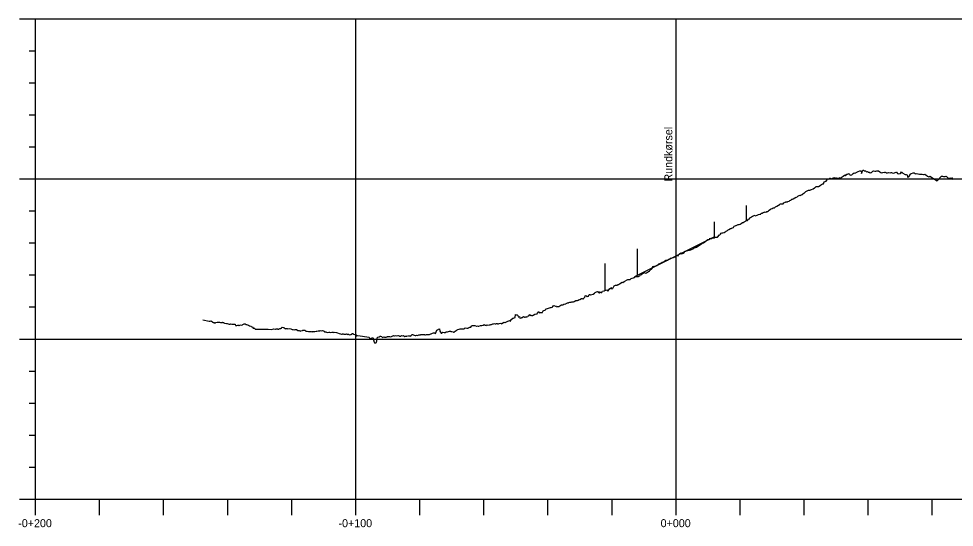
# Model space of a CAD drawing. Extents: x 0 to 513042, y 0 to 6212511.
# Drawn here: x 511927.8 to 512219.9, y 6211831.2 to 6211990 of the extents above; entities that cross this region are included whole.
import ezdxf

# ---------------------------------------------------------------- set-up
doc = ezdxf.new("R2010")
doc.units = 0
for name, color, linetype in [('TV_G_CL---', 7, 'Continuous'), ('TV_G_DTM_Exter', 7, 'Continuous'), ('TV_G_INF_SkrSg', 7, 'Continuous'), ('TV_L_---_Punkt', 7, 'Continuous'), ('TV_L_VER_Punkt', 7, 'Continuous')]:
    doc.layers.add(name, color=color, linetype=linetype)

msp = doc.modelspace()

# ---------------------------------------------------------------- linework, layer by layer
at = {"layer": 'TV_G_CL---'}
for q in [(511933.07, 6211990.01), (513033.07, 6211840.01)]:
    msp.add_line((511933.07, 6211840.01), q, dxfattribs=at)
at = {"layer": 'TV_G_DTM_Exter'}
for p, q in [((511928.07, 6211990.01), (511933.07, 6211990.01)), ((511928.07, 6211990.01), (511933.07, 6211990.01)), ((511931.07, 6211980.01), (511933.07, 6211980.01)), ((511931.07, 6211970.01), (511933.07, 6211970.01)), ((511931.07, 6211960.01), (511933.07, 6211960.01)), ((511931.07, 6211950.01), (511933.07, 6211950.01)), ((511928.07, 6211940.01), (511933.07, 6211940.01)), ((511931.07, 6211930.01), (511933.07, 6211930.01)), ((511931.07, 6211920.01), (511933.07, 6211920.01)), ((511931.07, 6211910.01), (511933.07, 6211910.01)), ((511931.07, 6211900.01), (511933.07, 6211900.01)), ((511928.07, 6211890.01), (511933.07, 6211890.01)), ((511931.07, 6211880.01), (511933.07, 6211880.01)), ((511931.07, 6211870.01), (511933.07, 6211870.01)), ((511931.07, 6211860.01), (511933.07, 6211860.01)), ((511931.07, 6211850.01), (511933.07, 6211850.01)), ((511928.07, 6211840.01), (511933.07, 6211840.01)), ((511933.07, 6211835.01), (511933.07, 6211840.01)), ((511953.07, 6211835.01), (511953.07, 6211840.01)), ((511973.07, 6211835.01), (511973.07, 6211840.01)), ((511993.07, 6211835.01), (511993.07, 6211840.01)), ((512013.07, 6211835.01), (512013.07, 6211840.01)), ((512033.07, 6211835.01), (512033.07, 6211840.01)), ((512053.07, 6211835.01), (512053.07, 6211840.01)), ((512073.07, 6211835.01), (512073.07, 6211840.01)), ((512093.07, 6211835.01), (512093.07, 6211840.01)), ((512113.07, 6211835.01), (512113.07, 6211840.01)), ((512133.07, 6211835.01), (512133.07, 6211840.01)), ((512153.07, 6211835.01), (512153.07, 6211840.01)), ((512173.07, 6211835.01), (512173.07, 6211840.01)), ((512193.07, 6211835.01), (512193.07, 6211840.01)), ((512213.07, 6211835.01), (512213.07, 6211840.01))]:
    msp.add_line(p, q, dxfattribs=at)
at = {"layer": 'TV_G_INF_SkrSg'}
msp.add_lwpolyline([(511985.36, 6211896.02), (511987.32, 6211895.56), (511987.55, 6211895.57), (511987.91, 6211895.64), (511988.47, 6211895.26), (511988.53, 6211895.2), (511988.73, 6211895.2), (511988.85, 6211895.15), (511989.11, 6211894.99), (511989.42, 6211895.15), (511989.78, 6211895.23), (511990.01, 6211895.23), (511990.53, 6211895.28), (511990.86, 6211895.16), (511991.04, 6211895.15), (511991.3, 6211895.18), (511991.48, 6211895.25), (511991.56, 6211895.12), (511991.78, 6211895.13), (511991.86, 6211895.08), (511992.12, 6211895.01), (511992.68, 6211894.84), (511992.88, 6211894.85), (511993.57, 6211894.62), (511993.87, 6211894.67), (511993.98, 6211894.71), (511994.41, 6211894.64), (511994.87, 6211894.67), (511995.19, 6211894.63), (511995.36, 6211894.6), (511995.53, 6211894.2), (511995.73, 6211894.2), (511995.9, 6211894.19), (511996.24, 6211894.34), (511996.42, 6211894.32), (511996.6, 6211894.24), (511996.69, 6211894.28), (511997.05, 6211894.44), (511997.35, 6211894.38), (511997.68, 6211894.43), (511997.82, 6211894.56), (511997.98, 6211894.64), (511998.26, 6211894.76), (511998.31, 6211894.7), (511998.53, 6211894.7), (511998.76, 6211894.53), (511998.89, 6211894.49), (511998.96, 6211894.53), (511999.58, 6211894.35), (511999.89, 6211894.14), (512000.3, 6211894.05), (512000.41, 6211893.89), (512000.86, 6211893.74), (512001.05, 6211893.42), (512001.47, 6211893.42), (512001.58, 6211893.27), (512001.67, 6211893.13), (512005.7, 6211893.04), (512006.73, 6211893.01), (512007.46, 6211893.15), (512007.86, 6211893.06), (512008.05, 6211893.06), (512008.22, 6211893.22), (512008.66, 6211893.15), (512008.77, 6211893.11), (512008.88, 6211893.08), (512009.09, 6211893.08), (512009.18, 6211893.22), (512009.31, 6211893.27), (512009.65, 6211893.33), (512009.89, 6211893.44), (512010.02, 6211893.75), (512010.04, 6211893.75), (512010.61, 6211893.58), (512011.13, 6211893.22), (512011.19, 6211893.25), (512011.54, 6211893.31), (512011.62, 6211893.26), (512011.81, 6211893.17), (512012.28, 6211893.3), (512012.77, 6211893.18), (512013.19, 6211893.03), (512013.49, 6211892.99), (512013.92, 6211892.92), (512014.18, 6211892.95), (512014.53, 6211892.94), (512014.94, 6211892.69), (512015.39, 6211892.62), (512015.8, 6211892.46), (512015.95, 6211892.53), (512016.42, 6211892.65), (512016.58, 6211892.81), (512017.09, 6211892.8), (512017.12, 6211892.8), (512017.5, 6211892.45), (512017.56, 6211892.48), (512017.85, 6211892.42), (512018.26, 6211892.36), (512018.62, 6211892.34), (512018.77, 6211892.33), (512018.9, 6211892.31), (512019.09, 6211892.31), (512019.46, 6211892.29), (512019.56, 6211892.34), (512019.74, 6211892.33), (512020.07, 6211892.32), (512020.27, 6211892.4), (512020.74, 6211892.43), (512020.87, 6211892.41), (512021.31, 6211892.52), (512021.88, 6211892.6), (512021.95, 6211892.63), (512022.28, 6211892.59), (512022.68, 6211892.69), (512022.76, 6211892.63), (512022.88, 6211892.59), (512023.16, 6211892.48), (512023.26, 6211892.3), (512023.76, 6211892.24), (512024.09, 6211892.01), (512024.62, 6211892.15), (512024.71, 6211892.12), (512024.83, 6211892.1), (512025.2, 6211892.08), (512025.6, 6211892.11), (512026, 6211892.19), (512026.01, 6211892.19), (512026.11, 6211892.09), (512026.5, 6211892.1), (512027.09, 6211892.07), (512027.41, 6211891.92), (512027.9, 6211891.73), (512028.27, 6211891.6), (512028.63, 6211891.56), (512028.79, 6211891.54), (512028.92, 6211891.59), (512029.12, 6211891.6), (512029.33, 6211891.54), (512029.41, 6211891.57), (512029.77, 6211891.54), (512030.04, 6211891.55), (512030.16, 6211891.61), (512030.58, 6211891.42), (512030.65, 6211891.55), (512030.86, 6211891.54), (512031.03, 6211891.31), (512031.48, 6211891.43), (512031.56, 6211891.47), (512032.02, 6211891.76), (512032.28, 6211891.72), (512032.35, 6211891.55), (512032.82, 6211891.45), (512032.94, 6211891.36), (512033.08, 6211891.35), (512033.26, 6211891.05), (512033.37, 6211891.02), (512033.72, 6211891.09), (512037.26, 6211890.56), (512037.39, 6211890.24), (512037.5, 6211890.21), (512037.92, 6211890.24), (512037.98, 6211890.27), (512038.21, 6211890.41), (512038.34, 6211890.49), (512038.79, 6211889.01), (512038.96, 6211888.86), (512039.34, 6211888.8), (512039.51, 6211888.94), (512039.81, 6211890.6), (512040.22, 6211890.68), (512040.5, 6211890.72), (512040.67, 6211890.9), (512040.81, 6211890.95), (512041.12, 6211890.78), (512041.43, 6211890.53), (512041.88, 6211890.72), (512042, 6211890.55), (512042.16, 6211890.62), (512042.57, 6211890.58), (512042.74, 6211890.64), (512042.87, 6211890.69), (512043.02, 6211890.76), (512043.2, 6211890.83), (512043.51, 6211890.76), (512043.59, 6211890.79), (512043.9, 6211890.74), (512044.23, 6211890.8), (512044.45, 6211890.9), (512044.87, 6211891.07), (512044.96, 6211891.02), (512045.1, 6211891.01), (512045.15, 6211891.03), (512045.42, 6211891.14), (512045.64, 6211891.04), (512046.18, 6211891.09), (512046.31, 6211891.07), (512046.62, 6211891.04), (512046.73, 6211890.93), (512046.84, 6211890.9), (512047.16, 6211890.93), (512047.35, 6211891.08), (512047.7, 6211891.04), (512047.96, 6211891.06), (512048.04, 6211891.01), (512048.33, 6211890.83), (512048.64, 6211890.87), (512049.04, 6211890.95), (512049.15, 6211891), (512049.21, 6211890.95), (512049.27, 6211890.97), (512049.44, 6211890.94), (512049.56, 6211891), (512049.92, 6211890.96), (512050.02, 6211890.93), (512050.32, 6211891.06), (512050.72, 6211891.37), (512050.85, 6211891.42), (512051, 6211891.33), (512051.29, 6211891.17), (512051.56, 6211891.11), (512051.85, 6211891.07), (512052.06, 6211891.16), (512052.46, 6211891.14), (512052.59, 6211891.22), (512052.8, 6211891.36), (512053.25, 6211891.28), (512053.31, 6211891.4), (512053.63, 6211891.38), (512053.83, 6211891.45), (512054.17, 6211891.41), (512054.53, 6211891.38), (512054.67, 6211891.28), (512054.82, 6211891.27), (512055.1, 6211891.38), (512055.7, 6211891.45), (512056.05, 6211891.43), (512056.52, 6211891.62), (512056.61, 6211891.66), (512057.07, 6211891.85), (512057.38, 6211891.98), (512057.66, 6211891.93), (512057.93, 6211891.78), (512058.39, 6211892.77), (512058.79, 6211893.02), (512058.89, 6211893.13), (512059.17, 6211893.16), (512059.34, 6211892.43), (512059.69, 6211891.88), (512059.91, 6211891.8), (512060.29, 6211892.12), (512060.64, 6211892.09), (512060.82, 6211892.08), (512061.01, 6211892.08), (512061.33, 6211892.3), (512061.56, 6211892.3), (512061.75, 6211892.3), (512062.02, 6211892.33), (512062.32, 6211892.46), (512062.64, 6211892.42), (512062.75, 6211892.38), (512063.08, 6211892.35), (512063.46, 6211892.26), (512063.59, 6211892.14), (512063.65, 6211892.17), (512063.8, 6211892.15), (512064.15, 6211892.47), (512064.42, 6211892.66), (512064.51, 6211892.7), (512064.57, 6211892.82), (512064.72, 6211892.88), (512064.96, 6211892.98), (512065.3, 6211893.04), (512065.65, 6211893.19), (512066.39, 6211893.24), (512066.76, 6211893.15), (512066.93, 6211893.22), (512067.17, 6211893.49), (512067.23, 6211893.49), (512067.77, 6211893.42), (512067.98, 6211893.42), (512068.16, 6211893.42), (512068.27, 6211893.47), (512068.64, 6211893.71), (512068.89, 6211893.73), (512068.97, 6211893.76), (512069.23, 6211894.04), (512069.34, 6211894.18), (512069.94, 6211894.19), (512070.09, 6211894.25), (512070.19, 6211894.2), (512070.71, 6211893.99), (512070.82, 6211894.04), (512071.12, 6211894.08), (512071.25, 6211894.05), (512071.48, 6211893.97), (512071.97, 6211894.18), (512072.46, 6211894.21), (512072.87, 6211894.38), (512073.19, 6211894.52), (512073.37, 6211894.33), (512073.53, 6211894.32), (512073.64, 6211894.28), (512074, 6211894.44), (512074.33, 6211894.33), (512074.68, 6211894.48), (512075.03, 6211894.45), (512075.2, 6211894.52), (512075.46, 6211894.55), (512075.87, 6211894.72), (512076.09, 6211894.73), (512076.41, 6211894.86), (512076.6, 6211894.77), (512076.76, 6211894.76), (512077.04, 6211894.88), (512077.18, 6211894.84), (512077.36, 6211894.76), (512077.62, 6211894.78), (512077.88, 6211894.89), (512078.4, 6211894.95), (512078.48, 6211894.82), (512078.66, 6211894.8), (512078.92, 6211894.92), (512079.25, 6211895.22), (512079.6, 6211895.19), (512079.65, 6211895.13), (512079.76, 6211895.17), (512079.87, 6211895.22), (512080.38, 6211895.51), (512081.03, 6211895.78), (512081.35, 6211895.6), (512081.59, 6211896.19), (512081.84, 6211896.11), (512082.13, 6211896.47), (512082.3, 6211896.55), (512082.5, 6211896.63), (512082.81, 6211896.76), (512082.94, 6211897.62), (512083.24, 6211897.56), (512083.32, 6211897.54), (512083.47, 6211897.6), (512083.69, 6211897.3), (512083.8, 6211896.94), (512083.94, 6211896.91), (512084.17, 6211897.01), (512084.3, 6211896.49), (512084.57, 6211896.6), (512084.62, 6211896.54), (512084.77, 6211896.61), (512084.92, 6211896.75), (512085.04, 6211896.72), (512085.48, 6211896.99), (512085.65, 6211896.9), (512085.77, 6211896.87), (512085.86, 6211896.82), (512085.92, 6211896.85), (512086.14, 6211896.94), (512086.58, 6211896.95), (512086.73, 6211897.1), (512087.15, 6211897.28), (512087.39, 6211897.62), (512087.44, 6211897.56), (512087.68, 6211897.39), (512087.78, 6211897.44), (512087.91, 6211897.32), (512088.37, 6211897.35), (512088.49, 6211897.49), (512089.02, 6211897.8), (512089.54, 6211897.86), (512089.68, 6211897.91), (512089.85, 6211898.15), (512090.04, 6211898.31), (512090.27, 6211898.58), (512090.41, 6211898.21), (512090.68, 6211898.24), (512091.1, 6211898.24), (512091.34, 6211898.34), (512091.39, 6211898.36), (512091.62, 6211898.82), (512091.79, 6211898.89), (512092.19, 6211899.06), (512092.37, 6211899.39), (512092.47, 6211899.43), (512092.63, 6211899.42), (512093.86, 6211899.86), (512094.09, 6211899.8), (512094.4, 6211900), (512094.57, 6211900.07), (512094.64, 6211900.37), (512094.78, 6211900.35), (512094.91, 6211900.48), (512095.41, 6211900.25), (512095.72, 6211900.3), (512095.84, 6211900.09), (512096.09, 6211900.11), (512096.3, 6211900.2), (512096.47, 6211900.18), (512096.75, 6211900.39), (512097.07, 6211900.61), (512097.32, 6211900.63), (512097.72, 6211900.71), (512098.04, 6211900.84), (512098.18, 6211900.9), (512098.66, 6211901.01), (512098.76, 6211901.14), (512099.14, 6211901.31), (512099.21, 6211901.34), (512099.46, 6211901.35), (512099.52, 6211901.38), (512099.6, 6211901.41), (512099.86, 6211901.52), (512100, 6211901.48), (512100.29, 6211901.52), (512100.49, 6211901.61), (512100.64, 6211901.59), (512101.04, 6211901.67), (512101.25, 6211901.76), (512101.8, 6211901.99), (512102.29, 6211902.02), (512102.55, 6211902.13), (512102.78, 6211902.31), (512102.91, 6211902.29), (512103.06, 6211902.35), (512103.51, 6211902.62), (512103.74, 6211902.63), (512103.94, 6211902.47), (512104.2, 6211902.66), (512104.28, 6211902.7), (512104.32, 6211902.8), (512104.6, 6211903.1), (512104.68, 6211903.46), (512104.9, 6211903.55), (512105.29, 6211903.32), (512105.74, 6211903.34), (512105.94, 6211903.9), (512106.1, 6211903.87), (512106.36, 6211903.83), (512106.47, 6211903.78), (512107.21, 6211904.02), (512107.65, 6211904.3), (512107.76, 6211904.5), (512108.27, 6211904.71), (512108.5, 6211904.81), (512108.88, 6211904.66), (512108.94, 6211904.84), (512108.97, 6211904.46), (512109.17, 6211904.46), (512109.37, 6211904.54), (512109.51, 6211904.69), (512109.67, 6211904.57), (512109.88, 6211904.57), (512109.98, 6211904.7), (512110.14, 6211904.95), (512110.6, 6211905.07), (512110.65, 6211905.09), (512110.89, 6211905.29), (512111, 6211905.24), (512111.28, 6211905.28), (512111.46, 6211905.35), (512111.72, 6211904.91), (512112.17, 6211905.47), (512112.38, 6211905.79), (512112.61, 6211905.82), (512112.74, 6211906.05), (512112.99, 6211905.69), (512113.09, 6211905.66), (512113.24, 6211906), (512113.42, 6211906), (512113.73, 6211906.6), (512114.16, 6211906.86), (512114.61, 6211906.78), (512114.73, 6211906.83), (512114.89, 6211906.95), (512114.91, 6211906.98), (512115.02, 6211907.02), (512115.17, 6211907.08), (512115.41, 6211907.19), (512116.27, 6211907.76), (512116.5, 6211907.7), (512116.84, 6211907.92), (512118, 6211908.55), (512118.2, 6211908.56), (512118.32, 6211908.62), (512118.61, 6211908.59), (512118.69, 6211908.63), (512119.09, 6211908.87), (512120.05, 6211909.21), (512120.34, 6211909.48), (512120.95, 6211909.57), (512121.3, 6211909.57), (512121.44, 6211909.63), (512121.74, 6211909.76), (512121.97, 6211910.15), (512122.18, 6211910.04), (512122.48, 6211910.31), (512122.95, 6211910.71), (512123, 6211910.74), (512123.3, 6211910.72), (512123.62, 6211910.56), (512123.79, 6211910.71), (512124.43, 6211911.07), (512124.51, 6211911.04), (512124.8, 6211911.24), (512125.02, 6211911.63), (512125.06, 6211911.65), (512125.3, 6211911.82), (512125.44, 6211911.78), (512125.58, 6211912.07), (512125.62, 6211912.15), (512125.88, 6211912.61), (512126.14, 6211912.72), (512126.28, 6211912.68), (512126.51, 6211912.77), (512126.82, 6211912.9), (512126.88, 6211912.93), (512126.93, 6211912.95), (512127.04, 6211912.92), (512127.59, 6211913.36), (512127.71, 6211913.48), (512128.01, 6211913.61), (512128.2, 6211913.59), (512128.36, 6211913.66), (512128.73, 6211914.01), (512128.81, 6211913.98), (512129.14, 6211914.11), (512129.22, 6211914.15), (512129.46, 6211914.35), (512129.54, 6211914.39), (512129.73, 6211914.54), (512129.89, 6211914.6), (512130.12, 6211914.6), (512130.44, 6211914.66), (512130.77, 6211914.9), (512130.89, 6211914.95), (512131.19, 6211915.15), (512131.36, 6211915.22), (512131.76, 6211915.39), (512131.88, 6211915.37), (512132.08, 6211915.45), (512132.27, 6211915.47), (512133.01, 6211915.78), (512133.17, 6211915.99), (512133.31, 6211916.12), (512133.36, 6211916.07), (512133.53, 6211916.07), (512133.72, 6211915.95), (512134.06, 6211916.59), (512134.13, 6211916.62), (512134.28, 6211916.69), (512134.6, 6211916.89), (512134.68, 6211916.85), (512134.81, 6211916.61), (512135.05, 6211916.72), (512135.26, 6211916.81), (512135.58, 6211917.02), (512135.72, 6211917.07), (512135.84, 6211917.41), (512136.12, 6211917.47), (512136.35, 6211917.56), (512137.67, 6211917.85), (512137.89, 6211918.01), (512138.41, 6211918.17), (512138.64, 6211918.34), (512139.32, 6211918.66), (512139.44, 6211918.7), (512141.15, 6211919.8), (512141.35, 6211919.89), (512141.54, 6211920.04), (512141.69, 6211920.03), (512141.91, 6211920.2), (512142.68, 6211920.85), (512142.96, 6211921.04), (512143.23, 6211921.09), (512143.32, 6211921.12), (512143.44, 6211920.97), (512143.52, 6211921.07), (512143.57, 6211921.5), (512143.96, 6211921.36), (512144.11, 6211921.43), (512144.44, 6211921.57), (512144.79, 6211921.62), (512144.96, 6211921.58), (512145.33, 6211921.86), (512145.63, 6211921.76), (512145.98, 6211921.84), (512146.6, 6211922.52), (512146.75, 6211922.58), (512146.92, 6211922.78), (512147.19, 6211923.02), (512147.51, 6211923.15), (512147.67, 6211923.21), (512148.09, 6211923.28), (512148.41, 6211923.48), (512148.52, 6211923.52), (512148.74, 6211923.71), (512149.13, 6211923.87), (512149.39, 6211924.05), (512149.55, 6211924.25), (512150.1, 6211924.47), (512150.26, 6211924.54), (512150.38, 6211924.59), (512150.52, 6211924.65), (512150.69, 6211924.71), (512151, 6211924.84), (512151.26, 6211925.23), (512151.5, 6211925.33), (512151.72, 6211925.42), (512151.8, 6211925.45), (512152.47, 6211925.72), (512152.74, 6211925.74), (512153.07, 6211925.88), (512153.36, 6211926.07), (512153.82, 6211926.36), (512153.98, 6211926.36), (512154.29, 6211926.56), (512154.76, 6211926.85), (512154.86, 6211926.96), (512155.34, 6211927.06), (512155.67, 6211927.42), (512156.01, 6211927.56), (512156.09, 6211927.89), (512156.53, 6211928.07), (512156.6, 6211928.11), (512156.9, 6211928.33), (512157.23, 6211928.47), (512157.38, 6211928.63), (512157.85, 6211928.52), (512158.08, 6211928.54), (512158.39, 6211928.67), (512158.8, 6211928.93), (512159.23, 6211928.96), (512159.5, 6211928.97), (512159.57, 6211929.1), (512159.79, 6211929.27), (512159.87, 6211929.3), (512160.01, 6211929.27), (512160.27, 6211929.44), (512160.28, 6211929.46), (512160.58, 6211929.57), (512160.7, 6211929.63), (512160.84, 6211929.69), (512161.15, 6211929.66), (512161.4, 6211929.85), (512161.62, 6211929.85), (512161.98, 6211930.08), (512162.19, 6211930.26), (512162.56, 6211930.59), (512162.74, 6211930.67), (512163.04, 6211930.79), (512163.35, 6211930.92), (512163.81, 6211931.01), (512163.95, 6211931.07), (512164.14, 6211931.24), (512164.56, 6211931.5), (512165.06, 6211931.8), (512165.23, 6211931.87), (512165.33, 6211931.91), (512165.47, 6211932.06), (512165.72, 6211932.24), (512165.85, 6211932.21), (512165.91, 6211932.24), (512166.25, 6211932.21), (512166.35, 6211932.25), (512166.48, 6211932.21), (512166.73, 6211932.49), (512167.21, 6211932.77), (512167.29, 6211932.8), (512167.86, 6211932.87), (512168.02, 6211932.94), (512168.36, 6211933.08), (512168.63, 6211933.28), (512168.95, 6211933.34), (512169.09, 6211933.48), (512169.16, 6211933.55), (512169.25, 6211933.63), (512169.46, 6211933.72), (512169.61, 6211933.78), (512170.12, 6211934.08), (512170.36, 6211934.18), (512170.46, 6211934.22), (512170.58, 6211934.27), (512170.69, 6211934.23), (512171.09, 6211934.58), (512171.68, 6211934.91), (512171.81, 6211934.79), (512172.07, 6211934.9), (512172.49, 6211935.16), (512172.72, 6211935.34), (512172.8, 6211935.46), (512173, 6211935.54), (512173.07, 6211935.57), (512173.14, 6211935.68), (512173.62, 6211936.05), (512173.81, 6211936.14), (512174, 6211936.3), (512174.45, 6211936.49), (512174.94, 6211936.53), (512175.07, 6211936.58), (512175.38, 6211936.71), (512175.91, 6211936.93), (512176.32, 6211937.19), (512176.42, 6211937.23), (512176.61, 6211937.4), (512176.84, 6211937.58), (512177.06, 6211937.58), (512177.07, 6211937.58), (512177.2, 6211937.64), (512177.65, 6211937.66), (512177.78, 6211937.72), (512178.15, 6211938.03), (512178.46, 6211938.25), (512178.82, 6211938.41), (512179.08, 6211938.51), (512179.34, 6211939.06), (512179.89, 6211939.29), (512180.37, 6211939.92), (512180.49, 6211939.98), (512180.74, 6211939.91), (512181.04, 6211940.28), (512181.2, 6211940.27), (512181.6, 6211940), (512182.3, 6211940.45), (512182.83, 6211940.25), (512182.94, 6211940.29), (512183.08, 6211940.34), (512183.41, 6211940.23), (512183.7, 6211940.18), (512183.95, 6211940.21), (512184.06, 6211940.33), (512184.32, 6211940.44), (512184.57, 6211940.37), (512184.92, 6211940.67), (512185.29, 6211940.83), (512185.66, 6211941.14), (512185.79, 6211941.19), (512185.94, 6211940.99), (512186, 6211941.01), (512186.41, 6211941.51), (512186.63, 6211941.52), (512186.85, 6211941.61), (512186.92, 6211941.55), (512187.13, 6211941.64), (512187.17, 6211941.66), (512187.32, 6211941.24), (512187.69, 6211941.12), (512187.97, 6211941.3), (512188.42, 6211941.73), (512188.64, 6211941.85), (512188.81, 6211941.84), (512189.2, 6211941.93), (512189.35, 6211941.99), (512189.96, 6211942.34), (512190.45, 6211942.47), (512190.58, 6211942.52), (512190.83, 6211942.51), (512190.92, 6211941.66), (512191.42, 6211942.68), (512191.61, 6211942.76), (512191.85, 6211942.48), (512192.24, 6211942.48), (512192.53, 6211942.2), (512192.85, 6211942.33), (512193.1, 6211942.11), (512193.36, 6211942.14), (512193.7, 6211941.88), (512194.03, 6211942.03), (512194.08, 6211942.05), (512194.52, 6211942.4), (512194.74, 6211942.5), (512195.09, 6211942.39), (512195.31, 6211942.41), (512195.45, 6211942.46), (512195.74, 6211942.5), (512196.31, 6211942.49), (512196.69, 6211942.23), (512196.98, 6211941.95), (512197.07, 6211941.9), (512197.48, 6211941.99), (512197.62, 6211942.05), (512198.09, 6211942.09), (512198.29, 6211942.01), (512198.48, 6211942.09), (512198.71, 6211941.93), (512198.95, 6211941.87), (512199.03, 6211941.9), (512199.13, 6211941.86), (512199.44, 6211941.99), (512200.03, 6211941.9), (512200.28, 6211942.01), (512200.34, 6211942.03), (512200.53, 6211941.94), (512200.96, 6211941.78), (512201.26, 6211941.91), (512201.28, 6211941.92), (512201.53, 6211942.02), (512201.83, 6211942.15), (512201.93, 6211942.11), (512202.26, 6211941.73), (512202.52, 6211941.59), (512203.17, 6211941.69), (512203.42, 6211942.21), (512203.51, 6211942), (512203.7, 6211942), (512203.76, 6211941.94), (512203.85, 6211941.81), (512204.57, 6211941.37), (512204.88, 6211941.33), (512205.08, 6211941.24), (512205.22, 6211941.3), (512205.31, 6211940.6), (512205.37, 6211940.55), (512205.78, 6211940.63), (512206.25, 6211941.49), (512206.41, 6211941.73), (512206.57, 6211941.72), (512207.13, 6211941.87), (512207.43, 6211941.91), (512207.59, 6211941.73), (512207.8, 6211941.57), (512208.03, 6211941.67), (512208.51, 6211941.54), (512208.63, 6211941.59), (512209.06, 6211941.43), (512209.51, 6211941.46), (512209.61, 6211941.5), (512209.95, 6211941.48), (512210.38, 6211941.33), (512210.58, 6211941.33), (512210.78, 6211941.5), (512211.04, 6211941.27), (512211.1, 6211941.3), (512211.58, 6211940.83), (512212.04, 6211940.68), (512212.27, 6211940.87), (512212.55, 6211940.72), (512213.23, 6211940.28), (512214.55, 6211939.42), (512214.62, 6211939.35), (512215.99, 6211940.84), (512216.3, 6211940.89), (512216.6, 6211940.77), (512216.79, 6211940.77), (512217.05, 6211940.71), (512217.37, 6211940.85), (512217.72, 6211940.57), (512217.96, 6211940.33), (512218.35, 6211940.16), (512218.41, 6211940.19), (512218.61, 6211940.19), (512218.84, 6211940.03), (512218.9, 6211940.06), (512219.07, 6211940.47), (512219.37, 6211939.92), (512219.78, 6211940.01), (512220, 6211940.02)], dxfattribs=at)
at = {"layer": 'TV_L_---_Punkt'}
for p, q in [((512133.07, 6211915.01), (512133.07, 6211950.8)), ((512155.1, 6211927.01), (512155.1, 6211931.7)), ((512145.07, 6211921.94), (512145.07, 6211926.63)), ((512145.07, 6211921.94), (512120.34, 6211909.48)), ((512121.07, 6211909.85), (512121.07, 6211918.18)), ((512110.89, 6211905.29), (512110.89, 6211913.62))]:
    msp.add_line(p, q, dxfattribs=at)
at = {"layer": 'TV_L_VER_Punkt'}
for p, q in [((511933.07, 6211990.01), (513033.07, 6211990.01)), ((511933.07, 6211990.01), (513033.07, 6211990.01)), ((512033.07, 6211840.01), (512033.07, 6211990.01)), ((512133.07, 6211840.01), (512133.07, 6211990.01)), ((511933.07, 6211940.01), (513033.07, 6211940.01)), ((511933.07, 6211890.01), (513033.07, 6211890.01))]:
    msp.add_line(p, q, dxfattribs=at)

# ---------------------------------------------------------------- texts
msp.add_text('Rundkørsel', height=2.5, rotation=90).set_placement((512131.9, 6211939.17))
for s, p in [('-0+200', (511927.67, 6211831.26)), ('-0+100', (512027.67, 6211831.26)), ('0+000', (512128.25, 6211831.26))]:
    msp.add_text(s, height=2.5).set_placement(p)

doc.saveas('drawing.dxf')
